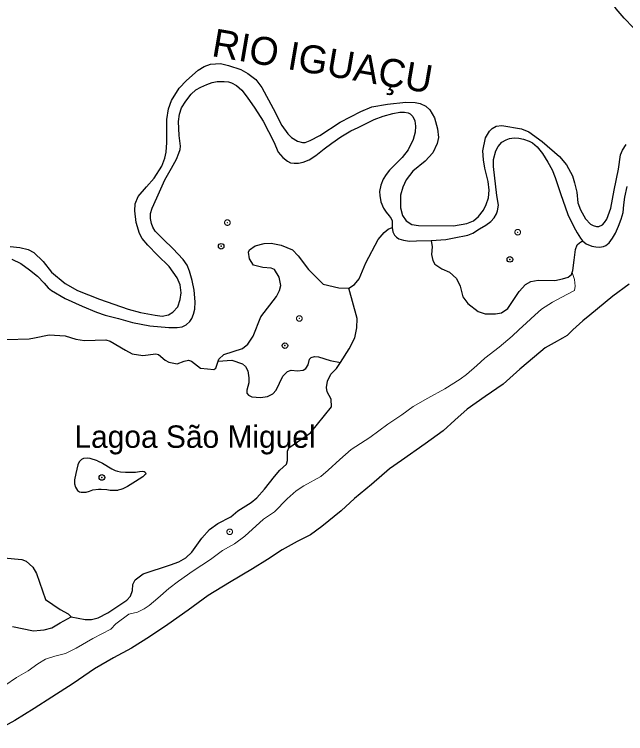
# Model space of a CAD drawing. Extents: x 267.7 to 296, y 7537.7 to 7565.8.
# Drawn here: x 276.556 to 278.742, y 7552.851 to 7555.422 of the extents above; entities that cross this region are included whole.
import ezdxf
from ezdxf.enums import TextEntityAlignment as Align

# ---------------------------------------------------------------- set-up
doc = ezdxf.new("R2010")
doc.units = 0
doc.header["$LTSCALE"] = 0.04
doc.header["$PDMODE"] = 32
doc.header["$PDSIZE"] = 0.02
doc.linetypes.add('SHORT_DASHED', pattern=[2.7, 1.5, -1.2])
for name, color, linetype, lineweight in [('2', 7, 'Continuous', 25), ('21', 7, 'SHORT_DASHED', 13), ('7', 7, 'Continuous', 25)]:
    doc.layers.add(name, color=color, linetype=linetype, lineweight=lineweight)
doc.layers.add('54', color=7, linetype='Continuous')
doc.layers.add('61', color=7, linetype='Continuous')

msp = doc.modelspace()

# ---------------------------------------------------------------- linework, layer by layer
at = {"layer": '2'}
for points in [[(278.7687, 7555.3753), (278.7374, 7555.4084), (278.7086, 7555.4422), (278.686, 7555.4798), (278.6616, 7555.523), (278.6485, 7555.5568), (278.6378, 7555.5994), (278.6341, 7555.6589), (278.6391, 7555.697), (278.6479, 7555.7171), (278.6629, 7555.7377), (278.6829, 7555.7559), (278.6911, 7555.7615), (278.6942, 7555.7665), (278.6961, 7555.7772), (278.6926, 7555.794)], [(276.5412, 7554.5921), (276.5762, 7554.5889), (276.6057, 7554.5814), (276.6257, 7554.5714), (276.6595, 7554.5388), (276.6896, 7554.5007), (276.7378, 7554.46), (276.7816, 7554.4355), (276.8611, 7554.4049), (276.9638, 7554.3686), (277.007, 7554.3567), (277.0595, 7554.3466), (277.0846, 7554.3441), (277.1078, 7554.3485), (277.1234, 7554.3579), (277.1409, 7554.3773), (277.1497, 7554.4036), (277.1528, 7554.4268), (277.1491, 7554.455), (277.1384, 7554.4806), (277.1103, 7554.5207), (277.0677, 7554.5614), (277.0333, 7554.5977), (277.0138, 7554.6209), (277.0038, 7554.639), (276.9919, 7554.6785), (276.9869, 7554.7198), (276.9882, 7554.7454), (276.9988, 7554.7717), (277.0289, 7554.8062), (277.0558, 7554.8368), (277.0833, 7554.88), (277.0946, 7554.9082), (277.099, 7554.9301), (277.1015, 7554.9646), (277.1015, 7555.0466), (277.1071, 7555.0848), (277.1178, 7555.1142), (277.1459, 7555.1586), (277.1716, 7555.1856), (277.2136, 7555.2225), (277.2355, 7555.2363), (277.2574, 7555.2444), (277.2931, 7555.2469), (277.3219, 7555.24), (277.3657, 7555.2256), (277.3907, 7555.2106), (277.4195, 7555.1893), (277.4414, 7555.1605), (277.4821, 7555.086), (277.5128, 7555.0253), (277.5341, 7554.9952), (277.5479, 7554.9821), (277.5685, 7554.9696), (277.5867, 7554.9646), (277.5961, 7554.9646), (277.6142, 7554.9714), (277.6487, 7554.989), (277.7219, 7555.0366), (277.7958, 7555.0754), (277.8346, 7555.0916), (277.8903, 7555.1017), (277.9561, 7555.1092), (277.9892, 7555.1079), (278.0074, 7555.1042), (278.0274, 7555.0948), (278.0425, 7555.081), (278.0587, 7555.0522), (278.07, 7555.0134), (278.0725, 7554.9821), (278.0688, 7554.9608), (278.0531, 7554.927), (278.0249, 7554.8982)], [(276.5479, 7554.5479), (276.5797, 7554.5316), (276.6106, 7554.5086), (276.6394, 7554.4865), (276.6629, 7554.4614), (276.6771, 7554.4447), (276.6892, 7554.4355), (276.7385, 7554.4066), (276.7983, 7554.379), (276.8497, 7554.3577), (276.8811, 7554.3468), (276.9287, 7554.3347), (276.9785, 7554.3209), (277.0403, 7554.3088), (277.1089, 7554.3025), (277.139, 7554.3025), (277.1561, 7554.3054), (277.1712, 7554.313), (277.1837, 7554.3243), (277.1913, 7554.3355), (277.1975, 7554.3506), (277.2013, 7554.3686), (277.2025, 7554.3945), (277.1996, 7554.4363), (277.1917, 7554.4714), (277.1829, 7554.5049), (277.1745, 7554.5258), (277.1599, 7554.5462), (277.1231, 7554.586), (277.0893, 7554.6177), (277.0604, 7554.647), (277.0512, 7554.662), (277.047, 7554.6746), (277.0433, 7554.6926), (277.0437, 7554.7105), (277.0491, 7554.7302), (277.0654, 7554.7665), (277.0947, 7554.8313), (277.1181, 7554.8723), (277.1365, 7554.9045), (277.1449, 7554.9258), (277.1495, 7554.9396), (277.1499, 7554.9513), (277.1453, 7554.9898), (277.1432, 7555.0395), (277.1465, 7555.0663), (277.1541, 7555.088), (277.1695, 7555.1127), (277.1883, 7555.1369), (277.2059, 7555.1524), (277.2226, 7555.1624), (277.2452, 7555.1721), (277.264, 7555.1787), (277.282, 7555.1821), (277.3062, 7555.1825), (277.3225, 7555.1813), (277.3334, 7555.1779), (277.3505, 7555.1683), (277.3702, 7555.1512), (277.3894, 7555.1265), (277.4158, 7555.0872), (277.4459, 7555.0408), (277.4847, 7554.9664), (277.5002, 7554.93), (277.5165, 7554.9108), (277.5336, 7554.8974), (277.5437, 7554.892), (277.5566, 7554.8903), (277.5729, 7554.8903), (277.5892, 7554.8936), (277.6101, 7554.9024), (277.634, 7554.9175), (277.6645, 7554.9421), (277.6912, 7554.9622), (277.7234, 7554.9844), (277.759, 7555.0061), (277.7861, 7555.0186), (277.8426, 7555.0466), (277.8756, 7555.0583), (277.9095, 7555.068), (277.9346, 7555.0726), (277.9517, 7555.0734), (277.9651, 7555.07), (277.9718, 7555.0667), (277.9818, 7555.0575), (277.9885, 7555.0425), (277.991, 7555.0224), (277.9897, 7555.0015), (277.9826, 7554.9756), (277.9642, 7554.9384)], [(277.9367, 7554.731), (277.9448, 7554.7029), (277.9573, 7554.6841), (277.978, 7554.6716), (278.0011, 7554.6672), (278.1263, 7554.6666), (278.1746, 7554.6747), (278.1983, 7554.6847), (278.2165, 7554.7004), (278.234, 7554.7223), (278.244, 7554.7423), (278.2516, 7554.7667), (278.2547, 7554.7943), (278.2503, 7554.8249), (278.2384, 7554.8725), (278.2334, 7554.902), (278.2315, 7554.9345), (278.2409, 7554.9815), (278.2553, 7555.0053), (278.2653, 7555.0146), (278.2797, 7555.0228), (278.2991, 7555.0247), (278.3693, 7555.0134), (278.3956, 7555.0021), (278.4438, 7554.9683), (278.5051, 7554.9145), (278.5302, 7554.8851), (278.5521, 7554.845), (278.559, 7554.8199), (278.5671, 7554.7874), (278.5715, 7554.7492), (278.5802, 7554.7235), (278.599, 7554.691), (278.6166, 7554.6722), (278.6266, 7554.6672), (278.6378, 7554.6641), (278.6466, 7554.6647), (278.6591, 7554.6697), (278.6666, 7554.6785), (278.6754, 7554.6903), (278.6898, 7554.7298), (278.7017, 7554.7943), (278.7161, 7554.8688), (278.7242, 7554.9201), (278.7311, 7554.9376), (278.7443, 7554.957)], [(278.0466, 7554.6144), (278.0993, 7554.6181), (278.1285, 7554.6232), (278.1783, 7554.6328), (278.1954, 7554.6403), (278.2197, 7554.6553), (278.2418, 7554.6691), (278.2602, 7554.6825), (278.2715, 7554.6951), (278.2803, 7554.7089), (278.284, 7554.7201), (278.287, 7554.7402), (278.2811, 7554.7749), (278.2694, 7554.8782), (278.2698, 7554.9037), (278.2778, 7554.935), (278.2865, 7554.9501), (278.2999, 7554.9651), (278.3146, 7554.9739), (278.3267, 7554.9789), (278.343, 7554.981), (278.3605, 7554.9802), (278.3764, 7554.976), (278.3969, 7554.9693), (278.409, 7554.963), (278.4262, 7554.9484), (278.445, 7554.9254), (278.4642, 7554.8941), (278.4797, 7554.8673), (278.4906, 7554.8389), (278.5098, 7554.782), (278.5357, 7554.7068), (278.5566, 7554.6625), (278.5683, 7554.6416), (278.5809, 7554.6227), (278.5883, 7554.6133)], [(277.9642, 7554.9384), (277.9429, 7554.9108), (277.8982, 7554.8656), (277.8861, 7554.8506), (277.8748, 7554.8339), (277.8672, 7554.8113)], [(278.0249, 7554.8982), (277.9811, 7554.8619), (277.9573, 7554.8312), (277.946, 7554.8049), (277.9373, 7554.7761), (277.9367, 7554.731)], [(277.8672, 7554.8113), (277.8626, 7554.7891), (277.8631, 7554.7745), (277.8672, 7554.7523), (277.876, 7554.7302), (277.8861, 7554.7155), (277.8969, 7554.7018), (277.904, 7554.6926), (277.907, 7554.6838), (277.9078, 7554.6601)], [(278.5883, 7554.6133), (278.6005, 7554.6027), (278.6214, 7554.5935), (278.6352, 7554.591), (278.6482, 7554.5901), (278.6636, 7554.5926), (278.6716, 7554.596), (278.6829, 7554.606), (278.6946, 7554.6227), (278.7063, 7554.6407), (278.7167, 7554.6654), (278.7259, 7554.69), (278.733, 7554.7139), (278.7355, 7554.741), (278.7389, 7554.7686), (278.7477, 7554.8075)], [(277.9078, 7554.6601), (277.9103, 7554.6453), (277.9157, 7554.6332), (277.9228, 7554.6257), (277.9316, 7554.6206), (277.9483, 7554.6148), (277.9688, 7554.6119), (277.9939, 7554.6123), (278.0466, 7554.6144)], [(278.7553, 7554.4585), (278.6968, 7554.4151), (278.6143, 7554.3468), (278.5886, 7554.3264), (278.5531, 7554.2945), (278.5327, 7554.2741), (278.5159, 7554.2643), (278.4866, 7554.2484), (278.4547, 7554.2306), (278.4166, 7554.1978), (278.3643, 7554.1535), (278.304, 7554.1003), (278.2402, 7554.0569), (278.1754, 7554.0107), (278.1311, 7553.9717), (278.0894, 7553.9336), (278.0256, 7553.8875), (277.9405, 7553.8272), (277.8979, 7553.7971), (277.8332, 7553.7421), (277.7729, 7553.6916), (277.725, 7553.6481), (277.6558, 7553.5914), (277.6151, 7553.5621), (277.5672, 7553.5382), (277.514, 7553.508), (277.4617, 7553.4734), (277.4085, 7553.44), (277.3259, 7553.3918), (277.2497, 7553.3446), (277.1779, 7553.292), (277.1049, 7553.2416), (277.0395, 7553.1976), (276.9751, 7553.1568), (276.9107, 7553.1225), (276.8431, 7553.0828), (276.767, 7553.0302), (276.6908, 7552.9808), (276.6275, 7552.9412), (276.5577, 7552.8982), (276.4719, 7552.851)], [(276.8531, 7553.8267), (276.828, 7553.8343), (276.8165, 7553.8361), (276.804, 7553.835), (276.797, 7553.8316), (276.7883, 7553.8225), (276.7838, 7553.8117), (276.7765, 7553.7811), (276.7716, 7553.7578), (276.772, 7553.7438), (276.7748, 7553.732), (276.7824, 7553.7205), (276.7897, 7553.716), (276.795, 7553.7146), (276.8033, 7553.7146), (276.8127, 7553.7146), (276.8245, 7553.7184), (276.8367, 7553.723), (276.8569, 7553.7254), (276.8667, 7553.7254), (276.8868, 7553.7233), (276.8987, 7553.7219), (276.9095, 7553.7216), (276.9209, 7553.7209), (276.9279, 7553.7212)], [(276.8531, 7553.8267), (276.8715, 7553.8183), (276.9049, 7553.7981), (276.9164, 7553.7922), (276.9255, 7553.7898), (276.9359, 7553.787), (276.954, 7553.7863), (276.9735, 7553.7853), (276.9892, 7553.786), (277.0038, 7553.7887), (277.0153, 7553.7898), (277.0208, 7553.7884), (277.024, 7553.7853), (277.0261, 7553.7811), (277.0254, 7553.7769), (277.0222, 7553.7745), (277.0156, 7553.7696), (276.9892, 7553.7529), (276.9606, 7553.7348), (276.9443, 7553.7257), (276.937, 7553.7233), (276.9279, 7553.7212)]]:
    msp.add_lwpolyline(points, dxfattribs=at)
msp.add_point((276.8694, 7553.7669), dxfattribs=at)
at = {"layer": '21'}
msp.add_lwpolyline([(276.5226, 7553.0235), (276.5643, 7553.0516), (276.606, 7553.0759), (276.6409, 7553.1002), (276.6681, 7553.1166), (276.701, 7553.1283), (276.7398, 7553.137), (276.7777, 7553.1564), (276.8369, 7553.1913), (276.9018, 7553.2243), (276.9193, 7553.2437), (276.9659, 7553.2777), (276.9969, 7553.2854), (277.0202, 7553.2971), (277.0386, 7553.3087), (277.0697, 7553.3349), (277.1085, 7553.3698), (277.1434, 7553.396), (277.1958, 7553.4329), (277.2579, 7553.4736), (277.3005, 7553.5056), (277.3432, 7553.5299), (277.3811, 7553.557), (277.447, 7553.6182), (277.4868, 7553.6444), (277.5314, 7553.6899), (277.5644, 7553.719), (277.5916, 7553.7375), (277.6527, 7553.7705), (277.6779, 7553.7928), (277.7206, 7553.8316), (277.7613, 7553.8665), (277.8273, 7553.9102), (277.8913, 7553.9577), (277.9418, 7553.9907), (277.9825, 7554.0207), (278.0349, 7554.0508), (278.096, 7554.0838), (278.1503, 7554.1187), (278.1726, 7554.1352), (278.2105, 7554.1672), (278.2386, 7554.1934), (278.29, 7554.2322), (278.3366, 7554.272), (278.3608, 7554.2943), (278.388, 7554.3195), (278.4171, 7554.3467), (278.4413, 7554.368), (278.4801, 7554.3932), (278.5121, 7554.4107), (278.5597, 7554.435), (278.5619, 7554.4503), (278.5598, 7554.4746), (278.5511, 7554.4996)], dxfattribs=at)
for p in [(277.3182, 7554.6781), (278.3562, 7554.6437), (277.5754, 7554.3352), (277.3265, 7553.5725)]:
    msp.add_point(p, dxfattribs=at)
at = {"layer": '54'}
for p in [(277.296, 7554.5934), (278.3283, 7554.5465), (277.5239, 7554.2381)]:
    msp.add_point(p, dxfattribs=at)
at = {"layer": '7'}
for points in [[(277.7519, 7554.4442), (277.7723, 7554.4573), (277.7896, 7554.4773), (277.8129, 7554.5343), (277.8574, 7554.618), (277.8791, 7554.6425), (277.8936, 7554.6545), (277.9078, 7554.6601)], [(277.2852, 7554.1827), (277.2874, 7554.1898), (277.3059, 7554.2065), (277.3718, 7554.2277), (277.3918, 7554.243), (277.4106, 7554.2724), (277.4381, 7554.3416), (277.4938, 7554.4143), (277.5047, 7554.4354), (277.509, 7554.4535), (277.5027, 7554.483), (277.4863, 7554.5105), (277.4744, 7554.5157), (277.4454, 7554.5179), (277.4116, 7554.5263), (277.3971, 7554.548), (277.3932, 7554.5724), (277.3977, 7554.581), (277.4169, 7554.5949), (277.4494, 7554.6039), (277.4742, 7554.6045), (277.5102, 7554.5975), (277.5515, 7554.5802), (277.5716, 7554.5588), (277.6077, 7554.5108), (277.6604, 7554.4577), (277.7167, 7554.4444), (277.7505, 7554.4433), (277.7519, 7554.4442)], [(278.0466, 7554.6144), (278.0507, 7554.5919), (278.0483, 7554.5642), (278.0533, 7554.5431), (278.0598, 7554.5299), (278.0845, 7554.5122), (278.112, 7554.5013), (278.1372, 7554.4784), (278.1507, 7554.4506), (278.1598, 7554.4132), (278.1775, 7554.3888), (278.2152, 7554.36), (278.2399, 7554.3519), (278.2766, 7554.3518), (278.2981, 7554.3559), (278.3208, 7554.3707), (278.3617, 7554.4319), (278.3846, 7554.4564), (278.4035, 7554.4672), (278.4296, 7554.4728), (278.4888, 7554.4708), (278.516, 7554.4772), (278.5362, 7554.4831), (278.5486, 7554.4924), (278.5511, 7554.4996)], [(278.5511, 7554.4996), (278.5537, 7554.5067), (278.5576, 7554.544), (278.5629, 7554.5817), (278.5691, 7554.5991), (278.5773, 7554.6063), (278.5883, 7554.6133)], [(277.7222, 7554.1782), (277.7535, 7554.2273), (277.7742, 7554.2665), (277.781, 7554.3024), (277.7824, 7554.3354), (277.7519, 7554.4442)], [(276.5292, 7554.2605), (276.6097, 7554.2625), (276.6287, 7554.2664), (276.6811, 7554.2771), (276.7386, 7554.2733), (276.7763, 7554.2613), (276.8073, 7554.2569), (276.8838, 7554.2585), (276.8994, 7554.2539), (276.9535, 7554.2224), (276.9771, 7554.2091), (277.0163, 7554.2025), (277.0625, 7554.2086), (277.0715, 7554.206), (277.0957, 7554.1857), (277.1089, 7554.1786), (277.1383, 7554.1733), (277.1641, 7554.1831), (277.1793, 7554.1865), (277.1899, 7554.1827), (277.2224, 7554.158), (277.2471, 7554.1557), (277.2701, 7554.1525), (277.2773, 7554.1573), (277.2852, 7554.1827)], [(277.2852, 7554.1827), (277.3338, 7554.186), (277.3727, 7554.1728), (277.3824, 7554.1635), (277.3912, 7554.1485), (277.3952, 7554.1236), (277.3949, 7554.1054), (277.3877, 7554.0787), (277.3881, 7554.0683), (277.3937, 7554.0606), (277.405, 7554.0555), (277.4361, 7554.0533), (277.4619, 7554.0566), (277.481, 7554.0664), (277.4929, 7554.0792), (277.5165, 7554.129), (277.5336, 7554.146), (277.5458, 7554.1506), (277.569, 7554.1482), (277.5889, 7554.1506), (277.5989, 7554.1563), (277.6073, 7554.1691), (277.6114, 7554.1896), (277.6177, 7554.1963), (277.6295, 7554.1995), (277.6443, 7554.1978), (277.6853, 7554.1855), (277.7222, 7554.1782)], [(276.7598, 7553.2689), (276.809, 7553.2591), (276.8325, 7553.2595), (276.8564, 7553.2649), (276.8902, 7553.2823), (276.959, 7553.3284), (276.9712, 7553.3425), (276.9786, 7553.3626), (276.9806, 7553.3847), (276.9883, 7553.4011), (277.0028, 7553.4116), (277.0169, 7553.422), (277.1153, 7553.454), (277.1444, 7553.4649), (277.1691, 7553.4796), (277.1913, 7553.5003), (277.2266, 7553.55), (277.2537, 7553.5803), (277.2835, 7553.6026), (277.3306, 7553.6265), (277.3557, 7553.6474), (277.4032, 7553.677), (277.4235, 7553.6945), (277.4513, 7553.7246), (277.4862, 7553.7708), (277.5057, 7553.7924), (277.529, 7553.8139), (277.5333, 7553.8278), (277.5333, 7553.8607), (277.5379, 7553.8726), (277.6153, 7553.9268), (277.6903, 7554.0195), (277.6895, 7554.0469), (277.6754, 7554.0726), (277.673, 7554.0883), (277.6758, 7554.1109), (277.6885, 7554.1358), (277.7087, 7554.1569), (277.7222, 7554.1782)], [(276.5183, 7553.4793), (276.583, 7553.4735), (276.5981, 7553.4677), (276.6225, 7553.4462), (276.6358, 7553.4233), (276.6682, 7553.331), (276.7199, 7553.2942), (276.7487, 7553.2792), (276.7598, 7553.2689)], [(276.5495, 7553.2345), (276.625, 7553.2179), (276.6502, 7553.2208), (276.663, 7553.2223), (276.6906, 7553.229), (276.7204, 7553.2466), (276.7598, 7553.2689)]]:
    msp.add_lwpolyline(points, dxfattribs=at)

# ---------------------------------------------------------------- texts
at = {"layer": '61'}
msp.add_text('RIO IGUAÇU', height=0.1, rotation=350.276, dxfattribs=at).set_placement((277.6501, 7555.2068), align=Align.CENTER)
msp.add_text('Lagoa São Miguel', height=0.08, dxfattribs=at).set_placement((276.7712, 7553.8728))

doc.saveas('drawing.dxf')
